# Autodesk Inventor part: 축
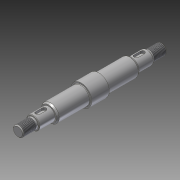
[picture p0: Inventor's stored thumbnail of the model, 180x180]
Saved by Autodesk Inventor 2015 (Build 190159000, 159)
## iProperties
Created: 2018-11
Part Number: 축
Material: 강철, 연강
Document SubType Name: Modeling
Designer: mduedu
Density: 1 g/cm^3
Appearance: 강철
Author: mduedu
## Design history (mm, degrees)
sketch "스케치1"
  geometry: L1 (-10, 0)-(10, 0); L2 (10, 0)-(10, 12); L3 (10, 12)-(-10, 12); L4 (-10, 12)-(-10, 0); L5 (-10, 0)-(-65, 0); L6 (-65, 0)-(-65, 7.5); L7 (-65, 7.5)-(-47, 7.5); L8 (-10, 7.5)-(-10, 0); L9 (-65, 0)-(-82, 0); L10 (-82, 0)-(-82, 6); L11 (-82, 6)-(-65, 6); L12 (-65, 6)-(-65, 0); L13 (0, 0)-(0, 12); L14 (10, 0)-(65, 0); L15 (65, 0)-(65, 7.5); L16 (65, 7.5)-(47, 7.5); L17 (10, 7.5)-(10, 0); L18 (65, 0)-(82, 0); L19 (82, 0)-(82, 6); L20 (82, 6)-(65, 6); L21 (65, 6)-(65, 0); L22 (-47, 7.5)-(-47, 8.85); L23 (-45.008, 10)-(-10, 10); L24 (10, 10)-(45.008, 10); L25 (47, 8.85)-(47, 7.5); L26 (-47, 8.85)-(-45.008, 10); L27 (47, 8.85)-(45.008, 10); 1 further point
  constraints: 54 end point, 9 parallel, 6 symmetric about line, 4 horizontal, 4 perpendicular, 2 midpoint, 2 point on line, 1 coincident
  dimensions: "d0" = 24 diameter of L3 L1; "d2" = 15 diameter of L7 L5; "d3" = 12 diameter of L11 L9; "d4" = 20 distance of L2.end L3.end; "d5" = 55 distance of L6.end L8.start; "d6" = 164 distance between parallel lines of L19 L10; "d24" = 20 diameter of L23 L5; "d25" = 18 distance of L6.end L7.end; "d26" = 18 distance of L15.end L16.end; "d27" = 20 diameter of L24 L14; "d28" = 55 distance between parallel lines of L15 L2; "d29" = 30 deg angle of L23 L26; "d30" = 17.7 diameter of L22.end L5; "d31" = 30 deg angle of L24 L27; "d32" = 17.7 diameter of L25.start L14
revolve "회전1" sketch "스케치1" stored, may be unused: angle "d7" = 90 deg
fillet "모깎기1" dims "d8" = 0.6
node "작업 평면1"
sketch "스케치2" dims "d11" = 12
  geometry: L1 (-3.5, 2.5)-(3.5, 2.5); L2 (3.5, 2.5)-(3.5, -2.5); L3 (3.5, -2.5)-(-3.5, -2.5); L4 (-3.5, -2.5)-(-3.5, 2.5); L5 (9, 7.5)-(9, -7.5) reference; 3 further points
  constraints: 8 end point, 2 midpoint, 2 parallel, 2 vertical alignment, 1 horizontal, 1 horizontal alignment, 1 perpendicular, 4 other
  dimensions: "d9" = 3 dimension on L5; "d10" = 5 distance between parallel lines of L3 L1
extrude "돌출1" cut sketch "스케치2" distance "d12" = 3; taper "d13" = 0 deg
chamfer "모따기1" distance "d14" = 0.5; stored, may be unused: second distance "d15" = 2, angle "d16" = 45 deg
feature "스레드1" dims "d17" = 15, "d18" = 0
feature "스레드2" dims "d19" = 15, "d20" = 0
chamfer "모따기2" distance "d21" = 1; stored, may be unused: second distance "d22" = 2, angle "d23" = 45 deg
node "솔리드1"
mirror "대칭1"
